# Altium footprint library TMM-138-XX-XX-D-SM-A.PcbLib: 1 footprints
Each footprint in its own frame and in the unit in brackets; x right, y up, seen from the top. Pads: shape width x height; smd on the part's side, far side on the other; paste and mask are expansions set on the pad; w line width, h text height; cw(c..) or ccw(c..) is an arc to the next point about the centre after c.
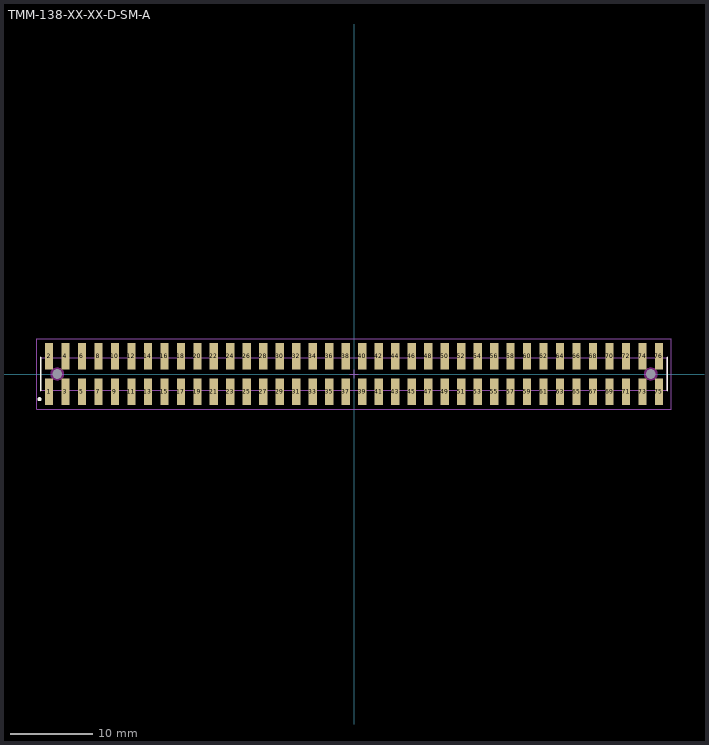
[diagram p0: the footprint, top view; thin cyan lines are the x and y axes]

## TMM-138-XX-XX-D-SM-A [mm] "2.00mm pitch, 76 pin, terminal strip; double row, w/alignment pins, SMT"
height 2.77
pads (78):
  rect 1x3.2 smd mask+0: 1(-37,-2.15) 2(-37,2.15) 3(-35,-2.15) 4(-35,2.15) 5(-33,-2.15) 6(-33,2.15) 7(-31,-2.15) 8(-31,2.15) 9(-29,-2.15) 10(-29,2.15) 11(-27,-2.15) 12(-27,2.15) 13(-25,-2.15) 14(-25,2.15) 15(-23,-2.15) 16(-23,2.15) 17(-21,-2.15) 18(-21,2.15) 19(-19,-2.15) 20(-19,2.15) 21(-17,-2.15) 22(-17,2.15) 23(-15,-2.15) 24(-15,2.15) 25(-13,-2.15) 26(-13,2.15) 27(-11,-2.15) 28(-11,2.15) 29(-9,-2.15) 30(-9,2.15) 31(-7,-2.15) 32(-7,2.15) 33(-5,-2.15) 34(-5,2.15) 35(-3,-2.15) 36(-3,2.15) 37(-1,-2.15) 38(-1,2.15) 39(1,-2.15) 40(1,2.15) 41(3,-2.15) 42(3,2.15) 43(5,-2.15) 44(5,2.15) 45(7,-2.15) 46(7,2.15) 47(9,-2.15) 48(9,2.15) 49(11,-2.15) 50(11,2.15) 51(13,-2.15) 52(13,2.15) 53(15,-2.15) 54(15,2.15) 55(17,-2.15) 56(17,2.15) 57(19,-2.15) 58(19,2.15) 59(21,-2.15) 60(21,2.15) 61(23,-2.15) 62(23,2.15) 63(25,-2.15) 64(25,2.15) 65(27,-2.15) 66(27,2.15) 67(29,-2.15) 68(29,2.15) 69(31,-2.15) 70(31,2.15) 71(33,-2.15) 72(33,2.15) 73(35,-2.15) 74(35,2.15) 75(37,-2.15) 76(37,2.15)
  round 1 hole 1.2 unplated mask+0: 77(-36,0) 78(36,0)
Top Overlay:
  circle w0.25: c-38.15,-3.05 r0.125
  lines w0.2: -38,-2 -38,2 ; 38,-2 38,2
Keep-Out Layer:
  pour cut-out: 36.807,0 36.779,0.209 36.699,0.403 36.57,0.571 36.403,0.699 36.209,0.779 36,0.807 35.791,0.779 35.596,0.699 35.429,0.571 35.301,0.403 35.22,0.209 35.193,0 35.22,-0.209 35.301,-0.403 35.429,-0.571 35.596,-0.699 35.791,-0.779 36,-0.807 36.209,-0.779 36.403,-0.699 36.57,-0.571 36.699,-0.403 36.779,-0.209
  pour cut-out: -35.193,0 -35.22,0.209 -35.301,0.403 -35.429,0.571 -35.596,0.699 -35.791,0.779 -36,0.807 -36.209,0.779 -36.403,0.699 -36.57,0.571 -36.699,0.403 -36.779,0.209 -36.807,0 -36.779,-0.209 -36.699,-0.403 -36.57,-0.571 -36.403,-0.699 -36.209,-0.779 -36,-0.807 -35.791,-0.779 -35.596,-0.699 -35.429,-0.571 -35.301,-0.403 -35.22,-0.209
Mechanical 12:
  lines w0.001: -38,-2 -38,2 38,2 38,-2 -38,-2
Mechanical 13:
  lines w0.1: -38,-2 -38,2 38,2 38,-2 -38,-2
  text ".Designator" at 0,-0.127 h1.52
Mechanical 15:
  lines w0.05: -0.5,0 0.5,0 ; 0,-0.5 0,0.5 ; -38.5,-4.3 -38.5,4.3 38.5,4.3 38.5,-4.3 -38.5,-4.3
